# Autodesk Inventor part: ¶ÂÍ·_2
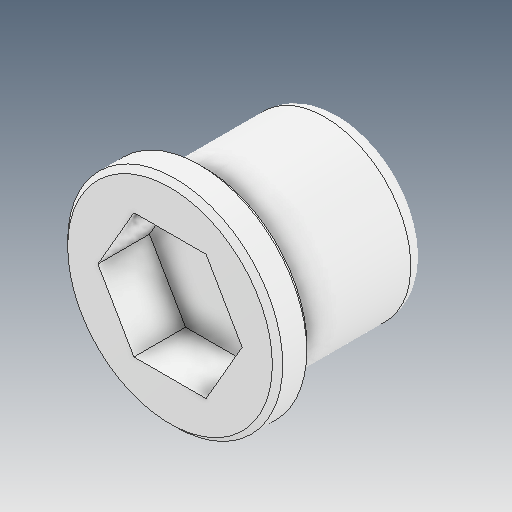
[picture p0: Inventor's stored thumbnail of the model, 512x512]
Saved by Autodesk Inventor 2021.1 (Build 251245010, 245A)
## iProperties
Created: 2021-06
Part Number: ¶ÂÍ·_2
Material: Ogólny
Document SubType Name: Modeling
Designer: user
Density: 1 g/cm^3
Appearance: Domyślna
Author: user
Revision Number: ÈÎºÎ
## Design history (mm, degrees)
feature "ÊäÈë1"
node "Bryła1"
